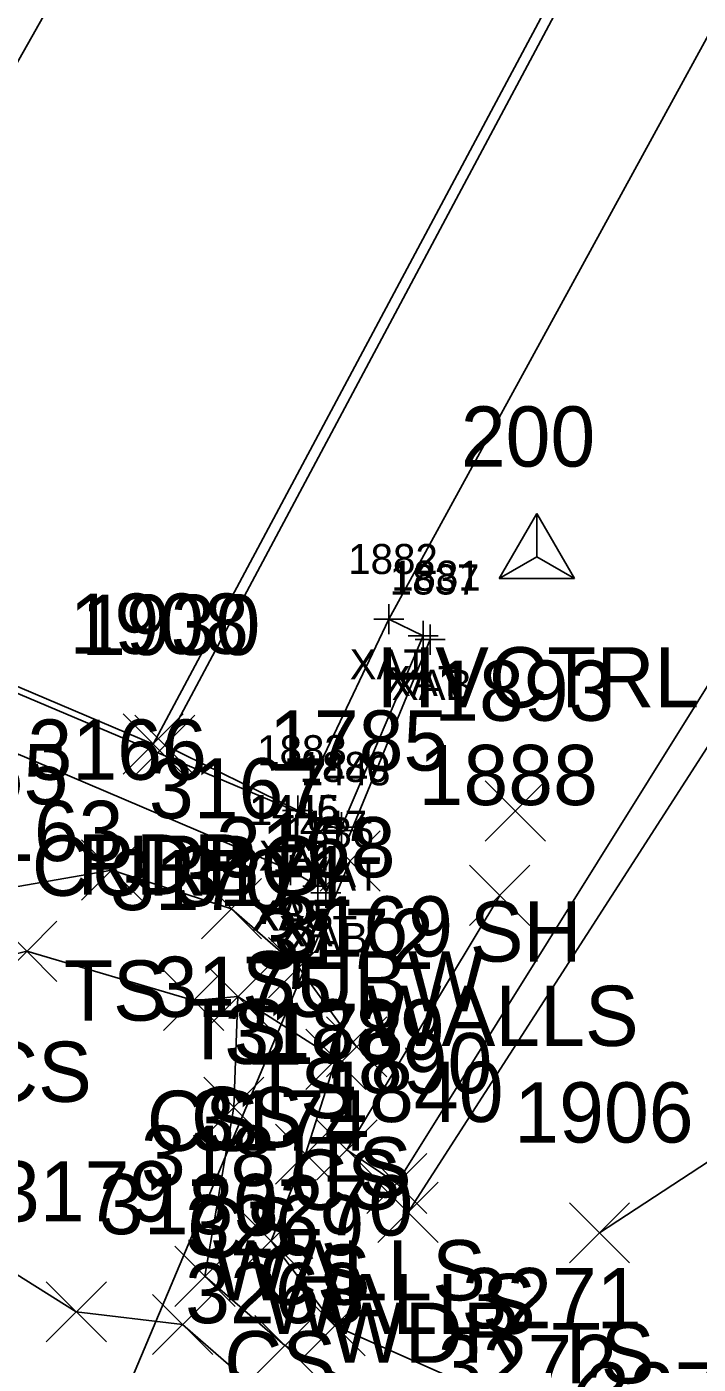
# Model space of a CAD drawing. Extents: x 462930 to 463548, y 29607 to 30453.
# Drawn here: x 463355.85 to 463362.64, y 30140.5 to 30154.04 of the extents above; entities that cross this region are included whole.
import ezdxf

# ---------------------------------------------------------------- set-up
doc = ezdxf.new("R2010")
doc.units = 0
for name, color, linetype in [('B_A', 7, 'Continuous'), ('B_I', 7, 'Continuous'), ('B_TIC', 7, 'Continuous'), ('BSE', 7, 'Continuous'), ('BSUBM', 7, 'Continuous'), ('C_A', 7, 'Continuous'), ('C_I', 7, 'Continuous'), ('CPSM', 7, 'Continuous'), ('L_A', 7, 'Continuous'), ('L_I', 7, 'Continuous'), ('L_TIC', 7, 'Continuous'), ('LASF', 7, 'Continuous'), ('LAWA', 7, 'Continuous'), ('LELB', 7, 'Continuous'), ('LWS', 7, 'Continuous'), ('P_A', 7, 'Continuous'), ('P_I', 7, 'Continuous'), ('P_TIC', 7, 'Continuous'), ('PET', 7, 'Continuous'), ('PRC', 7, 'Continuous'), ('R_A', 7, 'Continuous'), ('R_I', 7, 'Continuous'), ('R_TIC', 7, 'Continuous'), ('RC', 7, 'Continuous'), ('RSW', 7, 'Continuous'), ('U_A', 7, 'Continuous'), ('U_I', 7, 'Continuous'), ('U_TIC', 7, 'Continuous'), ('UW', 7, 'Continuous')]:
    doc.layers.add(name, color=color, linetype=linetype)

msp = doc.modelspace()

# ---------------------------------------------------------------- linework, layer by layer
at = {"layer": 'B_TIC'}
for p, q in [((463359.512, 30148.043), (463359.535, 30148.043)), ((463359.86, 30147.874), (463359.883, 30147.874)), ((463359.932, 30147.836), (463359.955, 30147.836)), ((463358.591, 30146.107), (463358.614, 30146.107)), ((463359.034, 30145.938), (463359.057, 30145.938)), ((463359.033, 30145.904), (463359.056, 30145.904)), ((463358.519, 30145.501), (463358.542, 30145.501)), ((463358.52, 30145.503), (463358.543, 30145.503)), ((463358.52, 30145.503), (463358.543, 30145.503)), ((463358.795, 30145.342), (463358.818, 30145.342)), ((463358.877, 30145.274), (463358.9, 30145.274))]:
    msp.add_line(p, q, dxfattribs=at)
for points in [[(463359.511, 30147.891), (463359.511, 30148.195)], [(463359.359, 30148.043), (463359.663, 30148.043)], [(463359.859, 30147.722), (463359.859, 30148.026)], [(463359.931, 30147.684), (463359.931, 30147.988)], [(463359.707, 30147.874), (463360.011, 30147.874)], [(463359.779, 30147.836), (463360.083, 30147.836)], [(463358.59, 30145.955), (463358.59, 30146.259)], [(463358.438, 30146.107), (463358.742, 30146.107)], [(463359.032, 30145.752), (463359.032, 30146.056)], [(463359.033, 30145.786), (463359.033, 30146.09)], [(463358.881, 30145.938), (463359.185, 30145.938)], [(463358.88, 30145.904), (463359.184, 30145.904)], [(463358.518, 30145.349), (463358.518, 30145.653)], [(463358.519, 30145.351), (463358.519, 30145.655)], [(463358.519, 30145.351), (463358.519, 30145.655)], [(463358.366, 30145.501), (463358.67, 30145.501)], [(463358.367, 30145.503), (463358.671, 30145.503)], [(463358.367, 30145.503), (463358.671, 30145.503)], [(463358.794, 30145.19), (463358.794, 30145.494)], [(463358.876, 30145.122), (463358.876, 30145.426)], [(463358.642, 30145.342), (463358.946, 30145.342)], [(463358.724, 30145.274), (463359.028, 30145.274)]]:
    msp.add_lwpolyline(points, dxfattribs=at)
at = {"layer": 'BSE'}
msp.add_lwpolyline([(463358.518, 30145.501), (463358.519, 30145.503)], dxfattribs=at)
at = {"layer": 'BSUBM'}
for points in [[(463358.519, 30145.503), (463358.794, 30145.342), (463359.032, 30145.904), (463348.028, 30150.565), (463347.822, 30150.053), (463348.078, 30149.95), (463348.08, 30149.95)], [(463348.08, 30149.95), (463358.518, 30145.501)], [(463359.033, 30145.938), (463359.859, 30147.874), (463359.511, 30148.043), (463358.59, 30146.107)], [(463358.876, 30145.274), (463359.931, 30147.836)], [(463358.59, 30146.107), (463359.033, 30145.938)]]:
    msp.add_lwpolyline(points, dxfattribs=at)
at = {"layer": 'CPSM'}
for p, q in [((463360.629, 30148.454), (463361.01, 30149.114)), ((463361.391, 30148.454), (463361.01, 30149.114)), ((463361.01, 30148.674), (463361.01, 30149.114)), ((463360.629, 30148.454), (463361.01, 30148.674)), ((463361.01, 30148.674), (463361.01, 30148.674)), ((463361.01, 30148.674), (463361.391, 30148.454)), ((463360.629, 30148.454), (463361.391, 30148.454))]:
    msp.add_line(p, q, dxfattribs=at)
at = {"layer": 'L_TIC'}
for points in [[(463360.487, 30145.796), (463361.097, 30146.406)], [(463361.097, 30145.796), (463360.487, 30146.406)], [(463356.404, 30145.199), (463357.014, 30145.808)], [(463357.014, 30145.199), (463356.404, 30145.808)], [(463360.329, 30144.942), (463360.939, 30145.552)], [(463360.939, 30144.942), (463360.329, 30145.552)], [(463357.616, 30144.807), (463358.225, 30145.417)], [(463358.225, 30144.807), (463357.616, 30145.417)], [(463355.545, 30144.376), (463356.155, 30144.985)], [(463356.155, 30144.376), (463355.545, 30144.985)], [(463358.296, 30144.211), (463358.906, 30144.821)], [(463358.906, 30144.211), (463358.296, 30144.821)], [(463357.234, 30143.879), (463357.843, 30144.489)], [(463357.843, 30143.879), (463357.234, 30144.489)], [(463357.681, 30143.918), (463358.29, 30144.528)], [(463358.29, 30143.918), (463357.681, 30144.528)], [(463357.681, 30143.918), (463358.29, 30144.528)], [(463358.29, 30143.918), (463357.681, 30144.528)], [(463358.881, 30143.409), (463359.491, 30144.018)], [(463359.491, 30143.409), (463358.881, 30144.018)], [(463358.671, 30143.283), (463359.281, 30143.893)], [(463359.281, 30143.283), (463358.671, 30143.893)], [(463357.64, 30142.797), (463358.249, 30143.407)], [(463358.249, 30142.797), (463357.64, 30143.407)], [(463358.365, 30142.322), (463358.975, 30142.931)], [(463358.975, 30142.322), (463358.365, 30142.931)], [(463358.783, 30142.366), (463359.393, 30142.976)], [(463359.393, 30142.366), (463358.783, 30142.976)], [(463359.288, 30142.025), (463359.898, 30142.635)], [(463359.898, 30142.025), (463359.288, 30142.635)], [(463359.401, 30141.734), (463360.011, 30142.344)], [(463360.011, 30141.734), (463359.401, 30142.344)], [(463361.338, 30141.526), (463361.948, 30142.136)], [(463361.948, 30141.526), (463361.338, 30142.136)], [(463358.016, 30141.445), (463358.626, 30142.054)], [(463358.626, 30141.445), (463358.016, 30142.054)], [(463357.347, 30141.086), (463357.956, 30141.696)], [(463357.956, 30141.086), (463357.347, 30141.696)], [(463356.045, 30140.726), (463356.655, 30141.336)], [(463356.655, 30140.726), (463356.045, 30141.336)], [(463357.121, 30140.598), (463357.731, 30141.208)], [(463357.731, 30140.598), (463357.121, 30141.208)], [(463358.662, 30140.584), (463359.271, 30141.194)], [(463359.271, 30140.584), (463358.662, 30141.194)], [(463358.156, 30140.385), (463358.766, 30140.994)], [(463358.766, 30140.385), (463358.156, 30140.994)]]:
    msp.add_lwpolyline(points, dxfattribs=at)
at = {"layer": 'LASF'}
msp.add_lwpolyline([(463335.666, 30151.825), (463339.994, 30150.186), (463344.731, 30148.092), (463345.991, 30147.14), (463346.905, 30145.251), (463349.408, 30144.305), (463351.788, 30143.206), (463354.335, 30142.295), (463356.35, 30141.031), (463357.426, 30140.903), (463358.46, 30140.002), (463361.001, 30139.273), (463362.41, 30138.437), (463365.572, 30136.833), (463366.432, 30136.349), (463367.765, 30135.728), (463368.18, 30135.769), (463368.592, 30135.381), (463370.057, 30136.689), (463370.978, 30134.911), (463374.408, 30132.631)], dxfattribs=at)
at = {"layer": 'LAWA'}
msp.add_lwpolyline([(463359.706, 30142.039), (463364.322, 30149.214), (463366.2, 30150.874), (463372.054, 30151.198), (463374.44, 30152.677), (463375.941, 30153.694), (463376.334, 30154.745), (463378.034, 30157.16), (463384.03, 30166.577), (463387.88, 30168.775), (463397.819, 30177.75)], dxfattribs=at)
at = {"layer": 'LELB'}
for points in [[(463315.632, 30161.314), (463319.611, 30159.411), (463323.098, 30158.045), (463326.567, 30156.56), (463329.582, 30155.13), (463332.054, 30154.159), (463333.762, 30152.444), (463336.134, 30152.447), (463340.253, 30150.769), (463345.161, 30149.365), (463346.778, 30148.746), (463346.708, 30147.71), (463349.033, 30147.393), (463350.898, 30147.395), (463351.713, 30147.754), (463353.797, 30146.756), (463354.253, 30145.629), (463355.291, 30145.255), (463356.709, 30145.503), (463357.92, 30145.112), (463358.601, 30144.516), (463359.186, 30143.714)], [(463338.725, 30147.014), (463341.902, 30146.288), (463346.905, 30145.251), (463349.39, 30146.891), (463350.92, 30147.048), (463352.297, 30147.355), (463353.139, 30145.924), (463354.358, 30144.307), (463355.85, 30144.681), (463357.539, 30144.184), (463357.985, 30144.223), (463357.945, 30143.102), (463357.652, 30141.391), (463358.461, 30140.69), (463361.001, 30139.273)], [(463361.643, 30141.831), (463367.08, 30145.391)], [(463357.985, 30144.223), (463358.976, 30143.588), (463358.67, 30142.627), (463358.321, 30141.75), (463358.966, 30140.889), (463361.075, 30139.951)]]:
    msp.add_lwpolyline(points, dxfattribs=at)
at = {"layer": 'LWS'}
msp.add_lwpolyline([(463360.634, 30145.247), (463359.088, 30142.671), (463359.593, 30142.33), (463364.17, 30149.664)], dxfattribs=at)
at = {"layer": 'P_TIC'}
for points in [[(463356.823, 30146.474), (463357.433, 30147.084)], [(463357.433, 30146.474), (463356.823, 30147.084)]]:
    msp.add_lwpolyline(points, dxfattribs=at)
at = {"layer": 'PET'}
for points in [[(463357.128, 30146.779), (463364.23, 30160.089), (463372.211, 30170.687), (463380.439, 30181.089), (463388.986, 30192.495), (463395.438, 30204.072), (463399.65, 30216.413), (463402.389, 30229.411), (463403.525, 30242.02), (463404.007, 30246.74), (463403.926, 30248.538), (463404.123, 30251.434)], [(463357.128, 30146.779), (463348.897, 30150.278)]]:
    msp.add_lwpolyline(points, dxfattribs=at)
at = {"layer": 'PRC'}
msp.add_lwpolyline([(463399.789, 30246.987), (463397.991, 30230.027), (463395.304, 30217.172), (463391.095, 30206.312), (463384.492, 30195.113), (463376.573, 30184.227), (463367.848, 30173.371), (463360.659, 30162.372), (463353.283, 30149.309)], dxfattribs=at)
at = {"layer": 'R_TIC'}
for points in [[(463356.941, 30146.462), (463357.551, 30147.072)], [(463357.551, 30146.462), (463356.941, 30147.072)]]:
    msp.add_lwpolyline(points, dxfattribs=at)
at = {"layer": 'RC'}
for points in [[(463403.888, 30243.164), (463403.731, 30243.164), (463403.598, 30241.759), (463402.492, 30229.375), (463399.74, 30216.359), (463395.506, 30204.018), (463389.016, 30192.435), (463380.487, 30181.016), (463372.297, 30170.609), (463364.316, 30160.034), (463357.246, 30146.767)], [(463357.246, 30146.767), (463358.59, 30146.107)]]:
    msp.add_lwpolyline(points, dxfattribs=at)
at = {"layer": 'RSW'}
msp.add_lwpolyline([(463365.586, 30159.156), (463359.511, 30148.043)], dxfattribs=at)
at = {"layer": 'U_TIC'}
for points in [[(463358.816, 30145.291), (463359.426, 30145.901)], [(463359.426, 30145.291), (463358.816, 30145.901)]]:
    msp.add_lwpolyline(points, dxfattribs=at)
at = {"layer": 'UW'}
msp.add_lwpolyline([(463344.573, 30111.096), (463359.121, 30145.596)], dxfattribs=at)

# ---------------------------------------------------------------- texts
at = {"layer": 'B_A'}
for s, p in [('XAT', (463359.116, 30147.433)), ('XAT', (463359.464, 30147.264)), ('XAB', (463359.541, 30147.226)), ('XAT', (463358.195, 30145.497)), ('XAT', (463358.637, 30145.294)), ('XAT', (463358.638, 30145.328)), ('XAT', (463358.124, 30144.893)), ('XBS', (463358.134, 30144.891)), ('XBS', (463358.135, 30144.893)), ('XAT', (463358.399, 30144.732)), ('XAB', (463358.486, 30144.664))]:
    msp.add_text(s, height=0.3048, dxfattribs=at).set_placement(p)
at = {"layer": 'B_I'}
for s, p in [('1882', (463359.101, 30148.5)), ('1881', (463359.535, 30148.331)), ('1837', (463359.521, 30148.293)), ('1883', (463358.18, 30146.564)), ('1880', (463358.609, 30146.395)), ('1448', (463358.622, 30146.361)), ('1446', (463358.1, 30145.96)), ('1446', (463358.1, 30145.96)), ('1445', (463358.108, 30145.958)), ('1447', (463358.384, 30145.799)), ('1836', (463358.457, 30145.731))]:
    msp.add_text(s, height=0.3048, dxfattribs=at).set_placement(p)
at = {"layer": 'C_A'}
msp.add_text('HVCTRL', height=0.6096, dxfattribs=at).set_placement((463359.392, 30147.15))
at = {"layer": 'C_I'}
msp.add_text('200', height=0.6096, dxfattribs=at).set_placement((463360.24, 30149.588))
at = {"layer": 'L_A'}
for s, p in [('SH', (463360.331, 30144.577)), ('TS', (463356.224, 30143.979)), ('WALLS', (463359.276, 30143.723)), ('TS', (463357.436, 30143.588)), ('CS', (463355.375, 30143.157)), ('TS', (463358.116, 30142.992)), ('CS', (463357.063, 30142.66)), ('CS', (463357.51, 30142.699)), ('CS', (463357.51, 30142.699)), ('TS', (463358.701, 30142.19)), ('CS', (463358.501, 30142.064)), ('CS', (463357.469, 30141.578)), ('WALLS', (463357.73, 30141.147)), ('CS', (463358.195, 30141.103)), ('WALLS', (463358.235, 30140.806)), ('WDR', (463358.902, 30140.515)), ('TS', (463361.158, 30140.307)), ('CS', (463357.846, 30140.226))]:
    msp.add_text(s, height=0.6096, dxfattribs=at).set_placement(p)
at = {"layer": 'L_I'}
for s, p in [('1893', (463359.971, 30147.015)), ('3166', (463355.857, 30146.418)), ('3165', (463354.456, 30146.169)), ('1888', (463359.813, 30146.161)), ('3167', (463357.085, 30146.026)), ('3163', (463355.015, 30145.595)), ('3168', (463357.766, 30145.43)), ('3170', (463356.691, 30145.098)), ('3171', (463357.338, 30145.138)), ('3171', (463357.338, 30145.138)), ('3169', (463358.348, 30144.628)), ('3172', (463358.155, 30144.502)), ('3175', (463357.124, 30144.017)), ('3173', (463357.849, 30143.541)), ('1889', (463358.265, 30143.585)), ('1890', (463358.746, 30143.244)), ('1840', (463358.859, 30142.953)), ('1906', (463360.781, 30142.745)), ('3174', (463357.501, 30142.664)), ('3181', (463357.004, 30142.306)), ('3179', (463355.527, 30141.946)), ('3180', (463356.579, 30141.817)), ('3270', (463357.946, 30141.804)), ('3269', (463357.451, 30141.604)), ('3268', (463357.452, 30140.916)), ('3271', (463360.254, 30140.865)), ('3271', (463360.254, 30140.865)), ('3272', (463360.007, 30140.188)), ('3272', (463360.007, 30140.188)), ('3274', (463361.496, 30139.909)), ('3274', (463361.496, 30139.909))]:
    msp.add_text(s, height=0.6096, dxfattribs=at).set_placement(p)
at = {"layer": 'P_A'}
msp.add_text('RDP', height=0.6096, dxfattribs=at).set_placement((463356.362, 30145.255))
at = {"layer": 'P_I'}
msp.add_text('1908', height=0.6096, dxfattribs=at).set_placement((463356.283, 30147.693))
at = {"layer": 'R_A'}
msp.add_text('CURBG', height=0.6096, dxfattribs=at).set_placement((463355.9, 30145.243))
at = {"layer": 'R_I'}
msp.add_text('1930', height=0.6096, dxfattribs=at).set_placement((463356.399, 30147.681))
at = {"layer": 'U_A'}
msp.add_text('SUBW', height=0.6096, dxfattribs=at).set_placement((463358.027, 30144.072))
at = {"layer": 'U_I'}
msp.add_text('1785', height=0.6096, dxfattribs=at).set_placement((463358.3, 30146.51))

doc.saveas('drawing.dxf')
